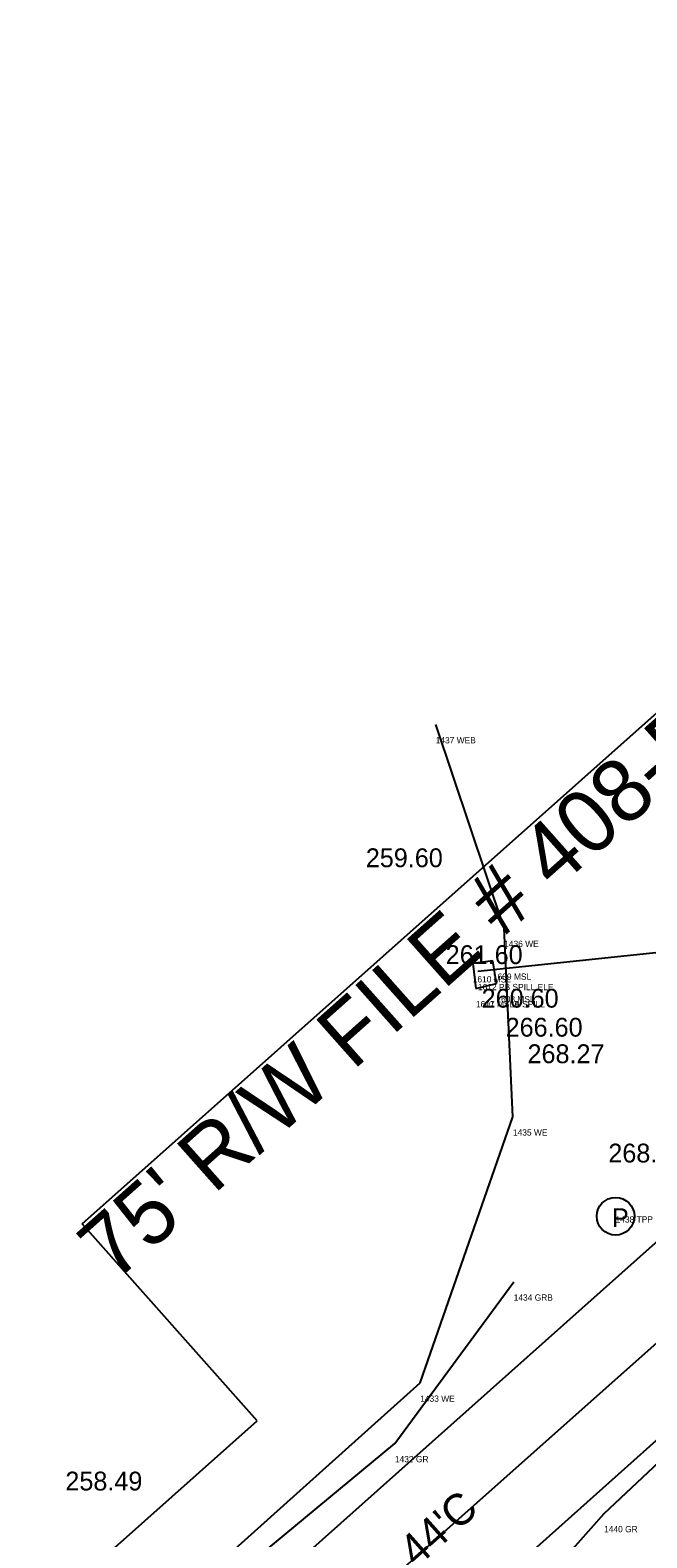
# Model space of a CAD drawing. Extents: x 49683 to 58852, y 49525 to 54803.
# Drawn here: x 55199.5 to 55297.8, y 53100.7 to 53340.9 of the extents above; entities that cross this region are included whole.
import ezdxf

# ---------------------------------------------------------------- set-up
doc = ezdxf.new("R2010")
doc.units = 0
for name, color, linetype in [('Level 1', 7, 'Continuous'), ('Level 10', 7, 'Continuous'), ('Level 13', 7, 'Continuous'), ('Level 2', 7, 'Continuous'), ('Level 25', 7, 'Continuous'), ('Level 3', 7, 'Continuous'), ('Level 32', 7, 'Continuous'), ('Level 48', 7, 'Continuous'), ('Level 52', 7, 'Continuous'), ('Level 56', 7, 'Continuous'), ('Level 57', 7, 'Continuous'), ('Level 59', 7, 'Continuous'), ('Level 6', 7, 'Continuous'), ('Level 60', 7, 'Continuous'), ('Level 7', 7, 'Continuous'), ('Level 9', 7, 'Continuous')]:
    doc.layers.add(name, color=color, linetype=linetype)

# ---------------------------------------------------------------- blocks, each defined once
blk = doc.blocks.new('TPP')
at = {"layer": 'Level 9'}
blk.add_circle((0, 0), 3, dxfattribs=at)
blk.add_text('P', height=3, dxfattribs=at).set_placement((-0.59, -1.73))

msp = doc.modelspace()

# ---------------------------------------------------------------- linework, layer by layer
at = {"layer": 'Level 1'}
msp.add_line((52544.81, 50683.3), (55534.58, 53340.86), dxfattribs=at)
at = {"layer": 'Level 10'}
for p, q in [((55275.06, 53197.81), (55264.14, 53230.24)), ((55276.45, 53167.77), (55275.06, 53197.81)), ((55261.67, 53125.36), (55276.45, 53167.77)), ((55223.63, 53091.32), (55261.67, 53125.36))]:
    msp.add_line(p, q, dxfattribs=at)
at = {"layer": 'Level 13'}
for p, q in [((55207.78, 53150.72), (55357.26, 53283.59)), ((55235.68, 53119.33), (55207.78, 53150.72)), ((54971.79, 52884.76), (55235.68, 53119.33))]:
    msp.add_line(p, q, dxfattribs=at)
at = {"layer": 'Level 2'}
for p, q in [((55273.26, 53192.59), (55270.04, 53192.16)), ((55270.04, 53192.16), (55270.55, 53188.21)), ((55273.81, 53188.98), (55273.26, 53192.59)), ((55270.55, 53188.21), (55273.81, 53188.98))]:
    msp.add_line(p, q, dxfattribs=at)
at = {"layer": 'Level 3'}
for p, q in [((55227.38, 53083.78), (55302.07, 53150.27)), ((55241.71, 53064.82), (55317.34, 53132.33))]:
    msp.add_line(p, q, dxfattribs=at)
at = {"layer": 'Level 6'}
msp.add_line((55307.3, 53194.72), (55270.87, 53190.93), dxfattribs=at)
at = {"layer": 'Level 7'}
for p, q in [((55257.64, 53115.73), (55276.57, 53141.47)), ((55290.98, 53104.58), (55316.81, 53128.89)), ((55225.18, 53088.89), (55257.64, 53115.73)), ((55265.86, 53076.33), (55290.98, 53104.58))]:
    msp.add_line(p, q, dxfattribs=at)

# ---------------------------------------------------------------- block references
at = {"layer": 'Level 9'}
msp.add_blockref('TPP', (55292.81, 53151.91), dxfattribs=at)

# ---------------------------------------------------------------- texts
at = {"layer": 'Level 25'}
msp.add_text("75' R/W FILE # 408-B", height=10, rotation=41.6333, dxfattribs=at).set_placement((55212.94, 53141.25))
at = {"layer": 'Level 32'}
for s, p in [('259.60', (55253, 53207.52)), ('261.60', (55265.73, 53192.09)), ('260.60', (55271.46, 53185.15)), ('266.60', (55275.28, 53180.53)), ('268.27', (55278.77, 53176.3)), ('268.75', (55291.65, 53160.48)), ('258.49', (55205.12, 53108.23))]:
    msp.add_text(s, height=3, dxfattribs=at).set_placement(p)
at = {"layer": 'Level 48'}
msp.add_text("44'C", height=5, rotation=41.6334, dxfattribs=at).set_placement((55261.11, 53095.87))
at = {"layer": 'Level 52'}
for s, p in [('1610 MSL', (55270.04, 53189.16)), ('1609 MSL', (55273.26, 53189.59)), ('1608 MSL', (55273.81, 53185.98)), ('1607 MSLA SPILL', (55270.55, 53185.21)), ('1611 MSLB SPILL', (55270.55, 53185.21))]:
    msp.add_text(s, height=1, dxfattribs=at).set_placement(p)
at = {"layer": 'Level 56'}
msp.add_text('1612 PB SPILL ELE', height=1, dxfattribs=at).set_placement((55270.87, 53187.93))
at = {"layer": 'Level 57'}
for s, p in [('1434 GRB', (55276.57, 53138.47)), ('1432 GR', (55257.64, 53112.73)), ('1440 GR', (55290.98, 53101.58))]:
    msp.add_text(s, height=1, dxfattribs=at).set_placement(p)
at = {"layer": 'Level 59'}
msp.add_text('1438 TPP', height=1, dxfattribs=at).set_placement((55292.81, 53150.91))
at = {"layer": 'Level 60'}
for s, p in [('1437 WEB', (55264.14, 53227.24)), ('1436 WE ', (55275.06, 53194.81)), ('1435 WE ', (55276.45, 53164.77)), ('1433 WE', (55261.67, 53122.36))]:
    msp.add_text(s, height=1, dxfattribs=at).set_placement(p)

doc.saveas('drawing.dxf')
